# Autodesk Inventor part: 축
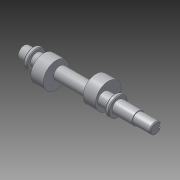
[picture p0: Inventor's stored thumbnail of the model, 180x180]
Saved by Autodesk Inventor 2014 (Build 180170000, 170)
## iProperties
Created: 2014-12
Part Number: 축
Material: 알루미늄 6061
Document SubType Name: Modeling
Designer: Owner
Density: 2.71 g/cm^3
Appearance: 알루미늄 - 평지
Mass: 182.114 g
Surface Area: 161.177 cm^2
Volume: 67.2007 cm^3
Author: Owner
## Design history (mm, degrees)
sketch "스케치1"
  geometry: L1 (-90, 0)-(90, 0); L2 (-90, 0)-(-90, 7.5); L3 (-90, 7.5)-(-66, 7.5); L4 (-66, 7.5)-(-66, 8.5); L5 (-66, 8.5)-(-39, 8.5); L6 (-39, 8.5)-(-39, 13); L7 (-39, 13)-(-34, 13); L8 (-34, 13)-(-34, 8.5); L9 (-34, 8.5)-(72, 8.5); L10 (72, 8.5)-(72, 13); L11 (72, 13)-(77, 13); L12 (77, 13)-(77, 8.5); L13 (77, 8.5)-(90, 8.5); L14 (90, 8.5)-(90, 0); 2 further points
  constraints: 28 end point, 10 parallel, 2 horizontal alignment, 2 perpendicular, 1 coincident, 1 horizontal, 1 midpoint, 1 vertical
  dimensions: "d0" = 180 distance of L1.start L1.end; "d1" = 15 diameter of L3 L1; "d2" = 17 diameter of L5 L1; "d3" = 26 diameter of L7 L1; "d4" = 26 diameter of L11 L1; "d5" = 24 distance of L2.end L3.end; "d6" = 27 distance of L4.end L5.end; "d7" = 5 distance of L6.end L7.end; "d8" = 13 distance of L12.end L13.end; "d9" = 5 distance of L10.end L11.end
revolve "회전1" sketch "스케치1" stored, may be unused: angle "d10" = 90 deg
node "작업 평면1"
sketch "스케치2"
  geometry: C1 r 17.5 at (0, 6); 1 further point
  constraints: 1 centre point, 1 vertical alignment
  dimensions: "d14" = 35 diameter of C1; "d15" = 6 distance of point (0, 0) C1.centre
extrude "돌출1" join sketch "스케치2" distance "d16" = 17; taper "d17" = 0 deg
node "작업 평면2"
sketch "스케치3"
  geometry: C1 r 17.5 at (0, -5); 1 further point
  constraints: 1 centre point, 1 vertical alignment
  dimensions: "d19" = 35 diameter of C1; "d20" = 5 distance of C1.centre point (0, 0)
extrude "돌출2" join sketch "스케치3" distance "d21" = 17; taper "d22" = 0 deg
node "작업 평면3"
sketch "스케치6"
  geometry: L1 (-12, -7.5)-(-12, 7.5) reference; L2 (-12, 2.5)-(5.5, 2.5); L3 (-12, -2.5)-(5.5, -2.5); L4 (-12, 2.5)-(-12, -2.5); A1 r 2.5 centre (5.5, 0) between (5.5, -2.5) and (5.5, 2.5); 2 further points
  constraints: 6 end point, 2 point on circle, 2 point on line, 1 centre point, 1 collinear, 1 midpoint, 1 parallel, 1 perpendicular
  dimensions: "d38" = 17.5 distance of L2.start L2.end; "d39" = 17.5 distance of L3.start L3.end; "d42" = 2.5 distance from line of L2 point (-12, 0); "d43" = 2.5 distance from line of L3 point (-12, 0); "d44" = 5 diameter of A1
extrude "돌출3" cut sketch "스케치6" distance "d45" = 3; taper "d46" = 0 deg
chamfer "모따기1" distance "d47" = 1; stored, may be unused: second distance "d48" = 2, angle "d49" = 45 deg
node "솔리드1"
other parameters: "d11" = -70.5, "d18" = -32.5
